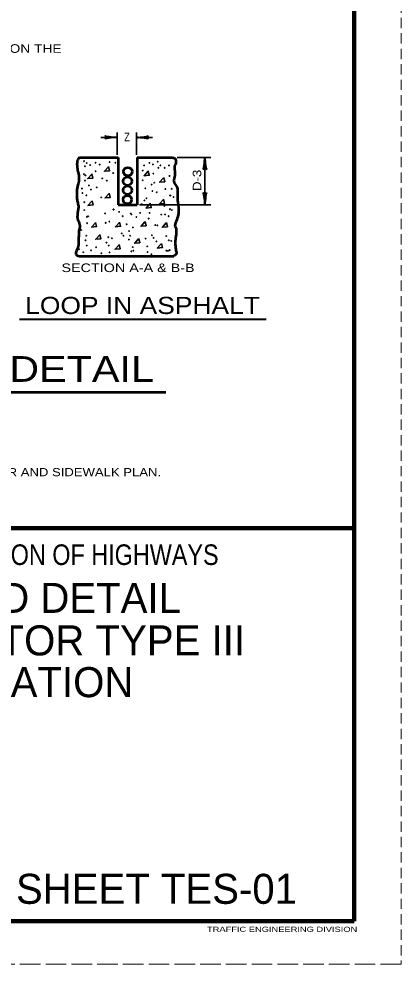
# Model space of a CAD drawing. Extents: x -58 to 622, y -372 to 68.
# Drawn here: x 532.5 to 621.6, y -372 to -151.8 of the extents above; entities that cross this region are included whole.
import ezdxf
from ezdxf.enums import TextEntityAlignment as Align

# ---------------------------------------------------------------- set-up
doc = ezdxf.new("R2010")
doc.units = 0
doc.header["$LTSCALE"] = 0.8
doc.linetypes.add('LONG_DASHED', pattern=[7.5, 6, -1.5])
doc.linetypes.add('MEDIUM_DASHED', pattern=[4.5, 3, -1.5])
doc.layers.add('1', color=7, linetype='Continuous', lineweight=35)
doc.layers.add('61', color=7, linetype='Continuous', lineweight=35)

msp = doc.modelspace()

# ---------------------------------------------------------------- linework, layer by layer
at = {"layer": '1', "linetype": 'MEDIUM_DASHED', "lineweight": 13}
msp.add_line((621.5902, 67.9933), (621.5702, -372.0267), dxfattribs=at)
at = {"layer": '1'}
for p, q in [((555.4188, -183.5127), (555.4188, -178.3408)), ((559.9188, -183.5127), (559.9188, -178.3408)), ((551.5907, -179.4547), (555.4108, -179.4547)), ((559.8657, -179.4547), (563.6857, -179.4547)), ((569.4138, -184.1492), (577.226, -184.1492)), ((575.8587, -184.0697), (575.8587, -195.1308)), ((560.6614, -195.1296), (577.226, -195.1296))]:
    msp.add_line(p, q, dxfattribs=at)
at = {"layer": '1', "lineweight": 53}
for p, q in [((546.6179, -184.13), (555.6179, -184.13)), ((555.6179, -184.13), (555.6179, -195.13)), ((560.1179, -184.13), (568.1179, -184.13)), ((560.1179, -184.13), (560.1179, -195.13)), ((555.6179, -195.13), (560.1179, -195.13)), ((546.6179, -207.13), (568.6179, -207.13)), ((475.4047, -238.811), (566.749, -238.811))]:
    msp.add_line(p, q, dxfattribs=at)
at = {"layer": '1', "lineweight": 40}
msp.add_line((532.6935, -221.7835), (590.1417, -221.7835), dxfattribs=at)
at = {"layer": '1'}
for points in [[(553.3868, -186.3156), (552.4655, -187.3521), (553.6555, -187.2369), (553.4252, -186.2388)], [(549.4881, -188.0263), (548.5667, -189.0628), (549.7568, -188.9477), (549.5264, -187.9496)], [(562.6167, -187.35), (561.6953, -188.3865), (562.8853, -188.2713), (562.655, -187.2732)], [(566.237, -188.8618), (565.3157, -189.8982), (566.5057, -189.7831), (566.2753, -188.785)], [(553.546, -192.5218), (552.6247, -193.5583), (553.8147, -193.4432), (553.5843, -192.4451)], [(549.5278, -194.2723), (548.6065, -195.3088), (549.7965, -195.1937), (549.5662, -194.1956)], [(563.0941, -194.8691), (562.1727, -195.9056), (563.3628, -195.7904), (563.1324, -194.7923)], [(566.1972, -193.9143), (565.2759, -194.9508), (566.4659, -194.8357), (566.2356, -193.8376)], [(550.3632, -199.3249), (549.4419, -200.3614), (550.6319, -200.2463), (550.4016, -199.2482)], [(555.933, -199.2453), (555.0117, -200.2818), (556.2017, -200.1667), (555.9713, -199.1686)], [(561.9006, -199.126), (560.9792, -200.1625), (562.1693, -200.0473), (561.9389, -199.0493)], [(566.8735, -199.3647), (565.9522, -200.4012), (567.1422, -200.286), (566.9118, -199.2879)], [(551.3579, -202.1495), (550.4366, -203.186), (551.6266, -203.0708), (551.3963, -202.0727)], [(555.8534, -204.457), (554.9321, -205.4935), (556.1221, -205.3783), (555.8918, -204.3802)], [(560.4286, -203.0646), (559.5072, -204.1011), (560.6972, -203.9859), (560.4669, -202.9878)], [(565.68, -204.2182), (564.7587, -205.2548), (565.9487, -205.1396), (565.7183, -204.1415)]]:
    msp.add_lwpolyline(points, dxfattribs=at)
at = {"layer": '1', "lineweight": 158}
msp.add_lwpolyline([(438.9702, -362.0467), (438.9702, -270.4667), (610.6302, -270.4667)], dxfattribs=at)
at = {"layer": '1'}
for centre in [(547.7259, -184.9931), (547.9248, -186.1866), (548.3227, -185.4307), (549.1183, -185.9081), (550.3914, -185.3512), (551.3462, -185.7887), (553.6537, -185.192), (555.0063, -185.3512), (561.3717, -187.1812), (561.69, -185.9877), (562.9232, -185.3909), (563.7587, -185.749), (564.8727, -185.1124), (565.0318, -186.5447), (565.5092, -185.9877), (566.464, -186.5447), (567.4984, -185.9877), (547.6861, -188.0167), (548.0442, -188.2952), (550.3914, -187.3403), (551.943, -189.0112), (554.4891, -187.7779), (563.8781, -187.8972), (567.6178, -188.4145), (547.2087, -191.3585), (547.9248, -189.5284), (548.8398, -190.6423), (549.3172, -191.5972), (550.6699, -191.1197), (553.0171, -189.5284), (561.3717, -189.4488), (562.0082, -191.3187), (563.4404, -190.4434), (564.077, -190.0058), (566.6629, -191.4778), (568.1349, -191.4381), (547.3281, -192.4327), (548.2431, -192.9498), (551.7043, -193.4272), (562.2469, -193.6262), (563.6394, -191.9553), (564.634, -192.2337), (567.7769, -192.9896), (568.5726, -193.3477), (547.7657, -194.5412), (561.133, -195.0186), (561.7695, -194.1433), (566.3844, -195.4164), (547.7657, -196.3713), (548.3624, -197.9626), (548.6807, -197.8432), (552.6192, -197.1669), (554.5687, -196.2518), (555.8816, -196.8088), (556.717, -197.8034), (558.5868, -197.2067), (558.746, -197.4056), (559.8997, -198.0023), (560.7749, -197.0476), (562.9631, -197.0476), (565.7082, -197.4454), (566.5833, -197.4056), (567.4188, -197.8034), (567.7371, -196.1723), (568.1748, -196.3713), (548.4022, -199.4346), (552.7387, -199.355), (553.6139, -199.0765), (557.632, -199.6732), (559.104, -200.4292), (562.7642, -198.3604), (564.3157, -199.8722), (564.7931, -199.9518), (547.0496, -201.0259), (548.2033, -202.3786), (556.4783, -201.8216), (556.8762, -202.3786), (558.189, -201.2646), (558.4277, -202.3786), (563.52, -202.2592), (566.8618, -202.4582), (548.0442, -203.4129), (548.3227, -204.6462), (552.9376, -203.9699), (553.3354, -202.6968), (553.4547, -204.6462), (554.2107, -202.9355), (558.1492, -203.2538), (562.048, -203.0151), (562.4458, -204.8452), (563.9178, -202.856), (564.5544, -203.6914), (567.4586, -203.4129), (568.0156, -203.5721), (546.5323, -205.5215), (547.527, -206.1978), (549.357, -205.7602), (550.5108, -205.0441), (551.744, -206.4365), (553.6537, -206.2376), (558.746, -205.9989), (559.0643, -205.0043), (559.2234, -205.8397), (562.5254, -206.158), (563.4007, -206.6753), (566.9017, -205.8397), (567.2597, -205.8795), (567.6575, -205.7204)]:
    msp.add_circle(centre, 0.0607, dxfattribs=at)
at = {"layer": '1', "lineweight": 53}
for centre in [(557.9164, -187.4319), (557.8368, -189.6598), (557.8368, -191.7683), (557.7971, -193.9564)]:
    msp.add_circle(centre, 1, dxfattribs=at)
at = {"layer": '1', "lineweight": 40}
for centre, major_axis, ratio, start_param, end_param in [((554.3196, -179.731), (1.7857, 0.1562), 0.122415, 0.89635335, 3.14159265), ((554.2902, -179.2431), (1.7565, -0.1757), 0.07063, 3.14071475, 5.41810995), ((560.9863, -179.6664), (1.7565, -0.1757), 0.07063, 6.28230741, 8.55970261), ((560.9569, -179.1785), (-1.7857, -0.1562), 0.122415, 0.89635335, 3.14159265), ((575.6471, -185.1902), (-0.1757, -1.7565), 0.07063, 6.28230741, 8.55970261), ((576.135, -185.1609), (-0.1562, 1.7857), 0.122415, 0.89635335, 3.14159265), ((575.5825, -194.0396), (0.1562, -1.7857), 0.122415, 0.89635335, 3.14159265), ((576.0704, -194.0102), (0.1757, 1.7565), 0.07063, 6.28230741, 8.55970261)]:
    msp.add_ellipse(centre, major_axis=major_axis, ratio=ratio, start_param=start_param, end_param=end_param, dxfattribs=at)
at = {"layer": '1', "lineweight": 53}
for points in [[(546.6179, -184.13), (546.22, -184.647), (546.0608, -185.6813), (546.1404, -186.8748), (546.4587, -188.3071), (546.3792, -190.1372), (546.0608, -191.6489), (546.0608, -192.2059), (546.0608, -193.7972), (546.22, -194.6725), (546.3792, -195.7864), (546.22, -196.7412), (546.1404, -197.6165), (546.1404, -198.253), (546.4587, -199.1282), (546.6974, -200.3217), (546.5382, -200.8787), (546.4587, -201.5152), (546.4587, -202.4701), (546.3792, -203.3453), (546.3792, -204.4592), (545.9812, -205.8119), (545.8222, -206.6872), (546.6179, -207.13)], [(568.1179, -184.13), (568.8172, -184.3287), (569.0558, -185.5222), (568.8172, -186.0792), (568.8967, -187.7501), (568.7376, -190.0576), (569.2945, -190.9328), (569.4537, -193.2403), (569.5332, -194.5133), (569.6923, -197.1391), (569.2945, -198.6508), (568.8967, -200.0035), (569.1354, -200.7196), (569.1354, -202.0722), (568.9762, -203.584), (568.9762, -204.4592), (569.0558, -205.4937), (569.215, -206.528), (568.6179, -207.13)]]:
    msp.add_spline(points, degree=3, dxfattribs=at)
at = {"layer": '61', "lineweight": 158}
for p, q in [((610.6102, 57.9933), (610.6302, -362.0467)), ((610.6302, -362.0467), (-28.4297, -362.0267))]:
    msp.add_line(p, q, dxfattribs=at)
at = {"layer": '61', "linetype": 'LONG_DASHED', "lineweight": 13}
msp.add_line((621.5702, -372.0267), (-58.4898, -372.0467), dxfattribs=at)

# ---------------------------------------------------------------- texts
at = {"layer": '1'}
for s, height, width, p in [('THE "X" DIMENSION SHALL BE 6 FOOT UNLESS OTHERWISE SPECIFIED ON THE', 2, 1.2, (418.0359, -159.7507)), ('REMOVE SIGN ON TYPE R CONDUIT ON TYPICAL GUTTER AND SIDEWALK PLAN.', 1.9, 1.2, (446.2252, -258.3905)), ('TRAFFIC ENGINEERING DIVISION', 1.2, 1.35, (576.3502, -364.5467))]:
    msp.add_text(s, height=height, dxfattribs=dict(at, width=width)).set_placement(p)
for s, height, width, p in [('Z', 2, 0.8, (557.7174, -180.3551)), ('SECTION A-A & B-B', 2, 1.25, (557.9562, -210.8294)), ('LOOP IN ASPHALT', 4, 1.15, (561.338, -220.6008)), ('SAW SLOT DETAIL', 6, 1.2, (520.9174, -236.4004)), ('WEST VIRGINIA DIVISION OF HIGHWAYS', 4.795, 0.85, (525.6186, -279.0667))]:
    msp.add_text(s, height=height, dxfattribs=dict(at, width=width)).set_placement(p, align=Align.CENTER)
at = {"layer": '1', "width": 1.15}
msp.add_text('D-3', height=2, rotation=90, dxfattribs=at).set_placement((575.0288, -189.4601), align=Align.CENTER)
at = {"layer": '1'}
for s, height, p in [('STANDARD DETAIL', 6.993, (526.8872, -290.2267)), ('LOOP DETECTOR TYPE III', 7, (526.4484, -300.1333)), ('INSTALLATION', 7, (525.9161, -309.8602))]:
    msp.add_text(s, height=height, dxfattribs=at).set_placement(p, align=Align.CENTER)
msp.add_text('STANDARD SHEET TES-01', height=6.993, dxfattribs=at).set_placement((477.8102, -358.0067))

doc.saveas('drawing.dxf')
